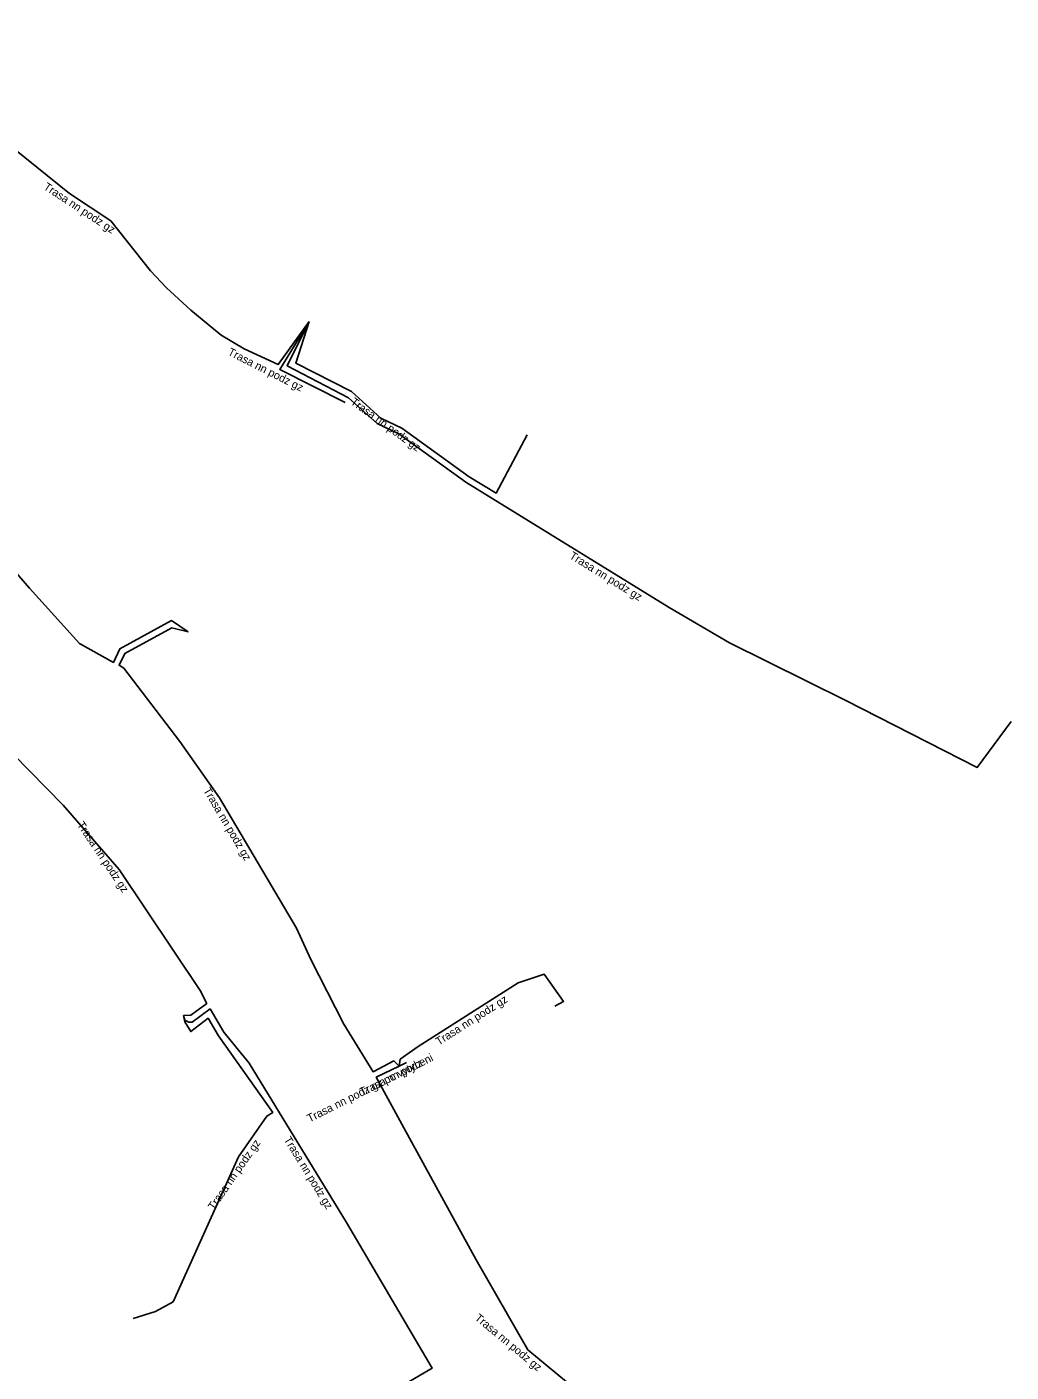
# Model space of a CAD drawing. Extents: x -484846 to -484244, y -1128177 to -1127608.
# Drawn here: x -484622.6 to -484561.1, y -1127855.5 to -1127771.4 of the extents above; entities that cross this region are included whole.
import ezdxf

# ---------------------------------------------------------------- set-up
doc = ezdxf.new("R2010")
doc.units = 0
doc.layers.add('Popiskový text - Ostatní atributy Trasy', color=7, linetype='Continuous')
doc.layers.add('Spojnice NN', color=7, linetype='Continuous')

msp = doc.modelspace()

# ---------------------------------------------------------------- linework, layer by layer
at = {"layer": 'Spojnice NN'}
for points in [[(-484604.929, -1127789.818), (-484606.857, -1127792.506), (-484608.99, -1127791.54), (-484610.41, -1127790.69), (-484612.32, -1127789.12), (-484613.83, -1127787.72), (-484614.83, -1127786.66), (-484617.31, -1127783.54), (-484619.9, -1127781.84), (-484624.74, -1127777.94), (-484627.894, -1127775.033), (-484624.877, -1127771.91), (-484624.811, -1127771.857), (-484625.133, -1127771.423), (-484625.314, -1127771.567)], [(-484635.629, -1127782.224), (-484637.563, -1127783.317), (-484637.73, -1127784), (-484635.56, -1127788.33), (-484636.53, -1127789.77), (-484633.55, -1127793.6), (-484622.4, -1127806.48), (-484619.27, -1127809.94), (-484617.154, -1127811.129), (-484616.742, -1127810.275), (-484613.517, -1127808.516), (-484612.492, -1127809.212)], [(-484602.681, -1127794.888), (-484606.745, -1127792.831), (-484604.929, -1127789.818)], [(-484561.073, -1127814.821), (-484563.191, -1127817.689), (-484571.39, -1127813.51), (-484578.67, -1127809.91), (-484582.43, -1127807.7), (-484593.454, -1127800.896), (-484595.14, -1127799.86), (-484599.33, -1127796.84), (-484600.67, -1127796.2), (-484602.461, -1127794.597), (-484606.298, -1127792.597), (-484604.929, -1127789.818)], [(-484591.312, -1127796.902), (-484593.245, -1127800.555), (-484594.918, -1127799.527), (-484599.125, -1127796.495), (-484600.444, -1127795.865), (-484602.269, -1127794.2), (-484605.762, -1127792.421), (-484604.929, -1127789.818)], [(-484612.492, -1127809.212), (-484613.503, -1127808.964), (-484616.438, -1127810.565), (-484616.794, -1127811.303), (-484616.5, -1127811.48), (-484613.01, -1127816.07), (-484610.53, -1127819.58), (-484605.72, -1127827.72), (-484604.81, -1127829.68), (-484602.76, -1127833.72), (-484600.932, -1127836.698), (-484599.634, -1127836.021), (-484599.31, -1127836.35)], [(-484624.774, -1127817.873), (-484623.422, -1127816.854), (-484620.29, -1127820.05), (-484616.79, -1127824.06), (-484611.73, -1127831.62), (-484611.321, -1127832.428), (-484612.314, -1127833.16), (-484612.768, -1127833.178)], [(-484599.31, -1127836.35), (-484599.236, -1127835.918), (-484598.11, -1127835.12), (-484591.87, -1127831.14), (-484590.25, -1127830.6), (-484589.03, -1127832.3), (-484589.581, -1127832.593)], [(-484612.768, -1127833.178), (-484612.687, -1127833.573), (-484612.318, -1127834.191), (-484611.234, -1127833.358), (-484610.584, -1127834.455), (-484607.198, -1127839.238), (-484607.57, -1127839.47), (-484609.33, -1127842.01), (-484613.41, -1127851.07), (-484614.52, -1127851.67), (-484615.922, -1127852.118)], [(-484612.768, -1127833.178), (-484612.693, -1127833.468), (-484612.446, -1127833.603), (-484612.242, -1127833.603), (-484611.117, -1127832.773), (-484610.256, -1127834.225), (-484608.677, -1127836.163), (-484602.59, -1127846.12), (-484597.23, -1127855.207), (-484598.852, -1127856.146), (-484598.8, -1127856.59)], [(-484599.31, -1127836.35), (-484600.728, -1127837.042), (-484599, -1127840.21), (-484594.48, -1127848.44), (-484591.27, -1127854.08), (-484588.85, -1127856.08), (-484584.69, -1127861.83), (-484580.782, -1127867.2), (-484579.454, -1127866.027), (-484580.399, -1127864.643), (-484580.014, -1127863.822)], [(-484598.85, -1127836.12), (-484599.31, -1127836.35)], [(-484598.85, -1127836.12), (-484599.31, -1127836.35)]]:
    msp.add_lwpolyline(points, dxfattribs=at)

# ---------------------------------------------------------------- texts
at = {"layer": 'Popiskový text - Ostatní atributy Trasy'}
for s, rotation, p in [('Trasa nn podz gz', 326.72028, (-484621.558, -1127781.529)), ('Trasa nn podz gz', 333.15368, (-484610.05, -1127791.887)), ('Trasa nn podz gz', 324.21957, (-484602.381, -1127794.949)), ('Trasa nn podz gz', 328.31716, (-484588.707, -1127804.59)), ('Trasa nn podz gz', 300.57923, (-484611.555, -1127819.122)), ('Trasa nn podz gz', 303.79488, (-484619.441, -1127821.269)), ('Trasa nn podz gz', 32.53057, (-484596.825, -1127835.072)), ('Trasa nn podz gz po vytyceni', 26.56505, (-484604.901, -1127839.872)), ('Trasa nn podz', 26.56505, (-484601.605, -1127838.224)), ('Trasa nn podz gz', 301.43864, (-484606.524, -1127840.931)), ('Trasa nn podz gz', 55.28139, (-484610.875, -1127845.382)), ('Trasa nn podz gz', 320.4281, (-484594.621, -1127852.154))]:
    msp.add_text(s, height=0.5, rotation=rotation, dxfattribs=at).set_placement(p)

doc.saveas('drawing.dxf')
